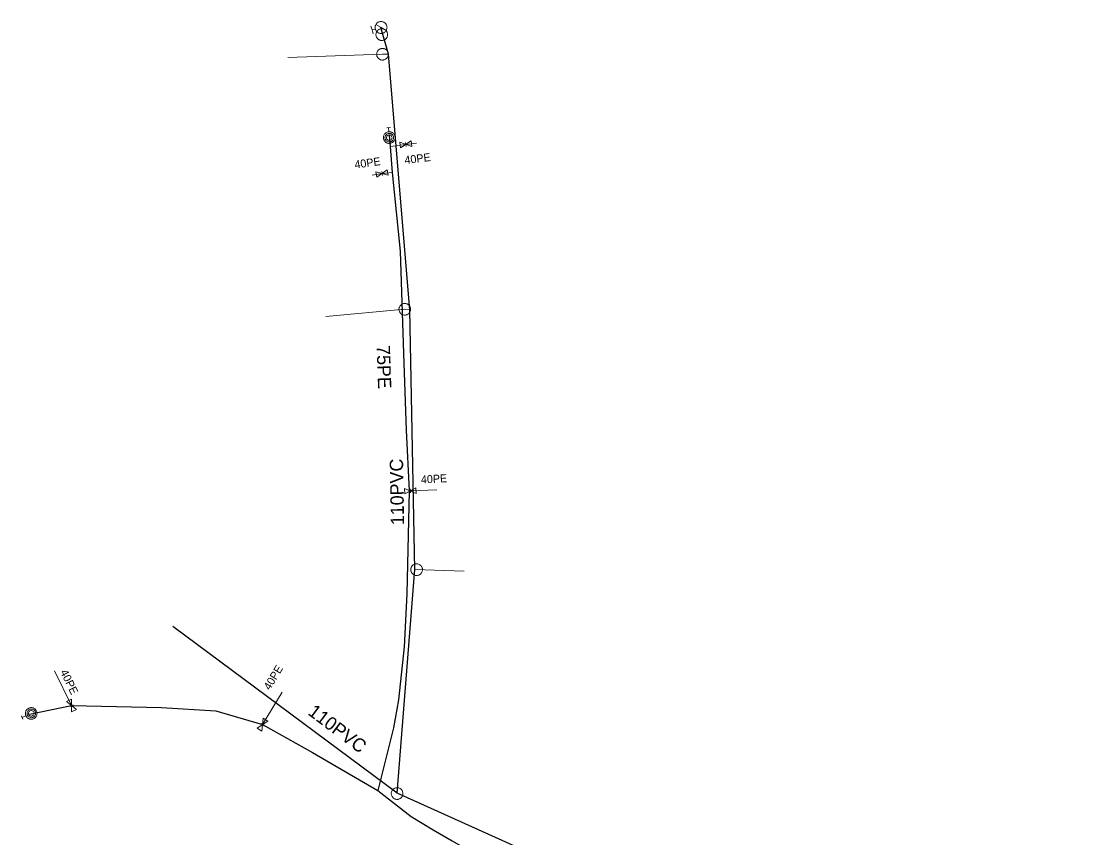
# Model space of a CAD drawing. Extents: x -741806 to -738704, y -1059275 to -1055387.
# Drawn here: x -740454.2 to -740373.8, y -1056915.4 to -1056854.3 of the extents above; entities that cross this region are included whole.
import ezdxf

# ---------------------------------------------------------------- set-up
doc = ezdxf.new("R2010")
doc.units = 0
doc.header["$LTSCALE"] = 0.4
for name, color, linetype, lineweight in [('2', 7, 'Continuous', 25), ('21', 7, 'Continuous', 13), ('37', 7, 'Continuous', 13), ('50', 7, 'Continuous', 13), ('51', 7, 'Continuous', 13), ('52', 7, 'Continuous', 25), ('56', 7, 'Continuous', 13)]:
    doc.layers.add(name, color=color, linetype=linetype, lineweight=lineweight)
for name, color, linetype in [('5', 7, 'Continuous'), ('53', 7, 'Continuous'), ('55', 7, 'Continuous')]:
    doc.layers.add(name, color=color, linetype=linetype)

msp = doc.modelspace()

# ---------------------------------------------------------------- linework, layer by layer
at = {"layer": '2'}
for points in [[(-740426.68, -1056862.84), (-740426.59, -1056863.659), (-740426.449, -1056865.61), (-740425.859, -1056871.5), (-740425.6, -1056879.159), (-740425.39, -1056884.909), (-740425.17, -1056889.46), (-740425.359, -1056897.179), (-740425.55, -1056901.139), (-740425.969, -1056905.1), (-740426.35, -1056907.2), (-740427.53, -1056911.899)], [(-740453.64, -1056906.19), (-740450.48, -1056905.54), (-740443.73, -1056905.679), (-740439.66, -1056905.94), (-740436.17, -1056906.97), (-740432.41, -1056909.06), (-740427.53, -1056911.899), (-740425.02, -1056913.86), (-740423.37, -1056914.86), (-740421.949, -1056915.679), (-740419.82, -1056916.909), (-740414.8, -1056920.01), (-740409.68, -1056923.179), (-740404.68, -1056925.79), (-740403.129, -1056927.36)]]:
    msp.add_lwpolyline(points, dxfattribs=at)
at = {"layer": '21'}
msp.add_line((-740424.752, -1056895.348), (-740421.048, -1056895.46), dxfattribs=at)
for points in [[(-740426.723, -1056856.754), (-740427.177, -1056856.75), (-740434.278, -1056856.993)], [(-740425.138, -1056875.886), (-740425.504, -1056875.855), (-740431.427, -1056876.394)]]:
    msp.add_lwpolyline(points, dxfattribs=at)
at = {"layer": '37'}
for p, q in [((-740426.856, -1056862.262), (-740426.585, -1056862.245)), ((-740426.702, -1056862.554), (-740426.721, -1056862.256)), ((-740425.43, -1056863.499), (-740425.446, -1056863.35)), ((-740425.43, -1056863.499), (-740425.413, -1056863.648)), ((-740427.209, -1056865.679), (-740427.235, -1056865.531)), ((-740427.209, -1056865.679), (-740427.183, -1056865.827)), ((-740425.09, -1056889.459), (-740425.096, -1056889.309)), ((-740425.09, -1056889.459), (-740425.083, -1056889.609)), ((-740450.48, -1056905.54), (-740450.615, -1056905.605)), ((-740450.48, -1056905.54), (-740450.345, -1056905.474)), ((-740454.124, -1056906.549), (-740454.231, -1056906.3)), ((-740453.901, -1056906.306), (-740454.175, -1056906.424)), ((-740436.17, -1056906.969), (-740436.298, -1056906.892)), ((-740436.17, -1056906.969), (-740436.042, -1056907.047))]:
    msp.add_line(p, q, dxfattribs=at)
for points in [[(-740426.234, -1056862.962), (-740426.239, -1056862.917), (-740426.249, -1056862.873), (-740426.263, -1056862.829), (-740426.282, -1056862.788), (-740426.306, -1056862.748), (-740426.333, -1056862.711), (-740426.364, -1056862.678), (-740426.398, -1056862.647), (-740426.436, -1056862.621), (-740426.475, -1056862.599), (-740426.518, -1056862.58), (-740426.562, -1056862.566), (-740426.606, -1056862.557), (-740426.652, -1056862.553), (-740426.698, -1056862.554), (-740426.743, -1056862.558), (-740426.788, -1056862.568), (-740426.831, -1056862.583), (-740426.873, -1056862.603), (-740426.913, -1056862.626), (-740426.949, -1056862.654), (-740426.983, -1056862.684), (-740427.013, -1056862.719), (-740427.04, -1056862.756), (-740427.062, -1056862.796), (-740427.08, -1056862.838), (-740427.094, -1056862.881), (-740427.103, -1056862.927), (-740427.107, -1056862.972), (-740427.107, -1056863.019), (-740427.101, -1056863.063), (-740427.091, -1056863.108), (-740427.076, -1056863.152), (-740427.058, -1056863.193), (-740427.034, -1056863.232), (-740427.007, -1056863.27), (-740426.976, -1056863.303), (-740426.942, -1056863.334), (-740426.904, -1056863.359), (-740426.864, -1056863.382), (-740426.822, -1056863.4), (-740426.778, -1056863.414), (-740426.734, -1056863.423), (-740426.688, -1056863.428), (-740426.642, -1056863.427), (-740426.596, -1056863.422), (-740426.552, -1056863.411), (-740426.509, -1056863.397), (-740426.467, -1056863.378), (-740426.427, -1056863.354), (-740426.391, -1056863.327), (-740426.357, -1056863.296), (-740426.327, -1056863.261), (-740426.3, -1056863.225), (-740426.278, -1056863.184), (-740426.259, -1056863.142), (-740426.246, -1056863.099), (-740426.237, -1056863.053), (-740426.233, -1056863.008), (-740426.234, -1056862.963)], [(-740453.674, -1056905.729), (-740453.714, -1056905.748), (-740453.753, -1056905.772), (-740453.789, -1056905.801), (-740453.822, -1056905.832), (-740453.851, -1056905.868), (-740453.877, -1056905.906), (-740453.898, -1056905.947), (-740453.915, -1056905.989), (-740453.927, -1056906.033), (-740453.935, -1056906.078), (-740453.938, -1056906.124), (-740453.937, -1056906.17), (-740453.93, -1056906.215), (-740453.919, -1056906.26), (-740453.903, -1056906.303), (-740453.883, -1056906.344), (-740453.859, -1056906.383), (-740453.83, -1056906.418), (-740453.798, -1056906.451), (-740453.762, -1056906.481), (-740453.724, -1056906.506), (-740453.684, -1056906.528), (-740453.641, -1056906.544), (-740453.598, -1056906.557), (-740453.552, -1056906.564), (-740453.506, -1056906.567), (-740453.461, -1056906.566), (-740453.415, -1056906.559), (-740453.371, -1056906.548), (-740453.327, -1056906.532), (-740453.287, -1056906.512), (-740453.249, -1056906.487), (-740453.212, -1056906.459), (-740453.18, -1056906.427), (-740453.15, -1056906.392), (-740453.124, -1056906.354), (-740453.104, -1056906.313), (-740453.086, -1056906.271), (-740453.075, -1056906.227), (-740453.067, -1056906.182), (-740453.063, -1056906.136), (-740453.065, -1056906.09), (-740453.072, -1056906.045), (-740453.082, -1056906), (-740453.099, -1056905.957), (-740453.119, -1056905.916), (-740453.144, -1056905.878), (-740453.171, -1056905.841), (-740453.204, -1056905.809), (-740453.239, -1056905.779), (-740453.277, -1056905.754), (-740453.317, -1056905.732), (-740453.36, -1056905.716), (-740453.404, -1056905.703), (-740453.45, -1056905.695), (-740453.496, -1056905.692), (-740453.54, -1056905.694), (-740453.587, -1056905.701), (-740453.631, -1056905.712), (-740453.673, -1056905.728)]]:
    msp.add_lwpolyline(points, dxfattribs=at)
for points in [[(-740426.347, -1056862.978), (-740426.357, -1056862.917), (-740426.379, -1056862.859), (-740426.411, -1056862.806), (-740426.453, -1056862.76), (-740426.503, -1056862.723), (-740426.558, -1056862.696), (-740426.618, -1056862.681), (-740426.681, -1056862.677), (-740426.742, -1056862.686), (-740426.801, -1056862.705), (-740426.855, -1056862.736), (-740426.902, -1056862.777), (-740426.94, -1056862.826), (-740426.968, -1056862.881), (-740426.986, -1056862.941), (-740426.991, -1056863.003), (-740426.984, -1056863.065), (-740426.965, -1056863.124), (-740426.936, -1056863.178), (-740426.896, -1056863.227), (-740426.849, -1056863.266), (-740426.794, -1056863.295), (-740426.735, -1056863.313), (-740426.673, -1056863.321), (-740426.611, -1056863.316), (-740426.551, -1056863.299), (-740426.496, -1056863.27), (-740426.447, -1056863.232), (-740426.406, -1056863.185), (-740426.375, -1056863.131), (-740426.355, -1056863.073), (-740426.347, -1056863.011)], [(-740426.461, -1056862.985), (-740426.47, -1056862.937), (-740426.49, -1056862.891), (-740426.521, -1056862.852), (-740426.56, -1056862.82), (-740426.606, -1056862.8), (-740426.655, -1056862.79), (-740426.704, -1056862.793), (-740426.753, -1056862.808), (-740426.795, -1056862.833), (-740426.831, -1056862.868), (-740426.857, -1056862.91), (-740426.873, -1056862.958), (-740426.877, -1056863.008), (-740426.869, -1056863.056), (-740426.849, -1056863.103), (-740426.82, -1056863.143), (-740426.78, -1056863.174), (-740426.736, -1056863.196), (-740426.687, -1056863.206), (-740426.637, -1056863.205), (-740426.589, -1056863.192), (-740426.545, -1056863.167), (-740426.509, -1056863.133), (-740426.482, -1056863.091), (-740426.465, -1056863.044), (-740426.46, -1056862.994)], [(-740425.021, -1056863.245), (-740425.838, -1056863.753), (-740425.884, -1056863.341), (-740424.975, -1056863.657)], [(-740427.601, -1056865.958), (-740426.818, -1056865.4), (-740426.746, -1056865.808), (-740427.673, -1056865.55)], [(-740424.665, -1056889.233), (-740425.514, -1056889.685), (-740425.532, -1056889.272), (-740424.647, -1056889.646)], [(-740450.856, -1056905.24), (-740450.104, -1056905.839), (-740450.476, -1056906.021), (-740450.484, -1056905.059)], [(-740453.62, -1056905.83), (-740453.675, -1056905.86), (-740453.722, -1056905.9), (-740453.761, -1056905.948), (-740453.79, -1056906.003), (-740453.809, -1056906.062), (-740453.815, -1056906.124), (-740453.809, -1056906.185), (-740453.792, -1056906.245), (-740453.763, -1056906.3), (-740453.725, -1056906.349), (-740453.678, -1056906.39), (-740453.624, -1056906.42), (-740453.565, -1056906.44), (-740453.503, -1056906.448), (-740453.441, -1056906.444), (-740453.381, -1056906.428), (-740453.325, -1056906.401), (-740453.276, -1056906.363), (-740453.235, -1056906.317), (-740453.202, -1056906.264), (-740453.181, -1056906.206), (-740453.172, -1056906.144), (-740453.175, -1056906.082), (-740453.189, -1056906.022), (-740453.214, -1056905.965), (-740453.25, -1056905.914), (-740453.295, -1056905.872), (-740453.348, -1056905.839), (-740453.405, -1056905.816), (-740453.467, -1056905.805), (-740453.529, -1056905.806), (-740453.589, -1056905.819)], [(-740453.575, -1056905.935), (-740453.618, -1056905.959), (-740453.655, -1056905.994), (-740453.681, -1056906.036), (-740453.697, -1056906.084), (-740453.701, -1056906.133), (-740453.694, -1056906.183), (-740453.674, -1056906.228), (-740453.645, -1056906.269), (-740453.607, -1056906.3), (-740453.562, -1056906.323), (-740453.513, -1056906.333), (-740453.463, -1056906.333), (-740453.415, -1056906.319), (-740453.371, -1056906.295), (-740453.334, -1056906.261), (-740453.307, -1056906.22), (-740453.29, -1056906.172), (-740453.284, -1056906.123), (-740453.291, -1056906.074), (-740453.309, -1056906.027), (-740453.338, -1056905.986), (-740453.376, -1056905.953), (-740453.421, -1056905.93), (-740453.469, -1056905.919), (-740453.519, -1056905.919), (-740453.567, -1056905.931)], [(-740436.122, -1056906.491), (-740436.217, -1056907.448), (-740436.572, -1056907.233), (-740435.768, -1056906.705)]]:
    msp.add_lwpolyline(points, close=True, dxfattribs=at)
at = {"layer": '50'}
for p, q in [((-740428.039, -1056854.633), (-740427.956, -1056854.928)), ((-740427.714, -1056854.86), (-740427.956, -1056854.928)), ((-740427.873, -1056855.225), (-740427.956, -1056854.928)), ((-740427.284, -1056854.738), (-740427.67, -1056854.519)), ((-740427.284, -1056854.738), (-740426.893, -1056854.958))]:
    msp.add_line(p, q, dxfattribs=at)
msp.add_lwpolyline([(-740427.4, -1056854.31), (-740427.447, -1056854.326), (-740427.49, -1056854.343), (-740427.531, -1056854.368), (-740427.567, -1056854.396), (-740427.601, -1056854.425), (-740427.633, -1056854.462), (-740427.659, -1056854.5), (-740427.683, -1056854.541), (-740427.703, -1056854.583), (-740427.715, -1056854.628), (-740427.725, -1056854.673), (-740427.732, -1056854.72), (-740427.729, -1056854.767), (-740427.724, -1056854.813), (-740427.715, -1056854.858), (-740427.699, -1056854.902), (-740427.682, -1056854.944), (-740427.657, -1056854.984), (-740427.629, -1056855.022), (-740427.597, -1056855.058), (-740427.563, -1056855.088), (-740427.525, -1056855.116), (-740427.484, -1056855.138), (-740427.443, -1056855.157), (-740427.397, -1056855.172), (-740427.352, -1056855.182), (-740427.306, -1056855.186), (-740427.258, -1056855.187), (-740427.212, -1056855.179), (-740427.166, -1056855.173), (-740427.121, -1056855.157), (-740427.079, -1056855.137), (-740427.04, -1056855.114), (-740427, -1056855.086), (-740426.967, -1056855.054), (-740426.935, -1056855.02), (-740426.909, -1056854.982), (-740426.884, -1056854.942), (-740426.866, -1056854.897), (-740426.853, -1056854.854), (-740426.843, -1056854.807), (-740426.839, -1056854.761), (-740426.838, -1056854.716), (-740426.843, -1056854.666), (-740426.853, -1056854.621), (-740426.868, -1056854.578), (-740426.888, -1056854.536), (-740426.911, -1056854.494), (-740426.938, -1056854.457), (-740426.971, -1056854.422), (-740427.005, -1056854.392), (-740427.044, -1056854.363), (-740427.083, -1056854.341), (-740427.125, -1056854.322), (-740427.171, -1056854.31), (-740427.216, -1056854.297), (-740427.263, -1056854.293), (-740427.309, -1056854.295), (-740427.355, -1056854.3)], close=True, dxfattribs=at)
at = {"layer": '51'}
for points in [[(-740426.793, -1056855.28), (-740426.794, -1056855.235), (-740426.802, -1056855.19), (-740426.814, -1056855.145), (-740426.83, -1056855.103), (-740426.851, -1056855.062), (-740426.875, -1056855.023), (-740426.905, -1056854.988), (-740426.937, -1056854.955), (-740426.973, -1056854.927), (-740427.011, -1056854.902), (-740427.052, -1056854.881), (-740427.095, -1056854.864), (-740427.139, -1056854.852), (-740427.184, -1056854.845), (-740427.23, -1056854.843), (-740427.276, -1056854.845), (-740427.321, -1056854.852), (-740427.365, -1056854.864), (-740427.407, -1056854.881), (-740427.449, -1056854.902), (-740427.487, -1056854.927), (-740427.522, -1056854.955), (-740427.554, -1056854.988), (-740427.584, -1056855.023), (-740427.608, -1056855.062), (-740427.63, -1056855.103), (-740427.646, -1056855.145), (-740427.657, -1056855.19), (-740427.665, -1056855.235), (-740427.668, -1056855.281), (-740427.665, -1056855.326), (-740427.657, -1056855.371), (-740427.646, -1056855.416), (-740427.63, -1056855.458), (-740427.608, -1056855.499), (-740427.584, -1056855.538), (-740427.554, -1056855.573), (-740427.522, -1056855.606), (-740427.487, -1056855.634), (-740427.449, -1056855.659), (-740427.407, -1056855.68), (-740427.365, -1056855.697), (-740427.321, -1056855.708), (-740427.276, -1056855.716), (-740427.23, -1056855.718), (-740427.184, -1056855.716), (-740427.139, -1056855.708), (-740427.095, -1056855.697), (-740427.052, -1056855.68), (-740427.011, -1056855.659), (-740426.973, -1056855.634), (-740426.937, -1056855.606), (-740426.905, -1056855.573), (-740426.875, -1056855.538), (-740426.851, -1056855.499), (-740426.83, -1056855.458), (-740426.814, -1056855.416), (-740426.802, -1056855.371), (-740426.794, -1056855.326), (-740426.793, -1056855.281)], [(-740427.613, -1056856.745), (-740427.612, -1056856.79), (-740427.605, -1056856.835), (-740427.594, -1056856.88), (-740427.578, -1056856.922), (-740427.557, -1056856.964), (-740427.533, -1056857.003), (-740427.504, -1056857.038), (-740427.472, -1056857.071), (-740427.437, -1056857.1), (-740427.399, -1056857.125), (-740427.358, -1056857.146), (-740427.315, -1056857.164), (-740427.271, -1056857.176), (-740427.226, -1056857.184), (-740427.18, -1056857.186), (-740427.134, -1056857.184), (-740427.089, -1056857.178), (-740427.045, -1056857.166), (-740427.002, -1056857.15), (-740426.961, -1056857.129), (-740426.923, -1056857.104), (-740426.886, -1056857.077), (-740426.854, -1056857.044), (-740426.825, -1056857.009), (-740426.799, -1056856.97), (-740426.778, -1056856.93), (-740426.762, -1056856.888), (-740426.749, -1056856.843), (-740426.742, -1056856.798), (-740426.739, -1056856.752), (-740426.741, -1056856.707), (-740426.748, -1056856.662), (-740426.759, -1056856.617), (-740426.775, -1056856.575), (-740426.796, -1056856.533), (-740426.82, -1056856.494), (-740426.849, -1056856.459), (-740426.881, -1056856.426), (-740426.916, -1056856.397), (-740426.954, -1056856.372), (-740426.995, -1056856.351), (-740427.038, -1056856.333), (-740427.082, -1056856.322), (-740427.127, -1056856.313), (-740427.173, -1056856.311), (-740427.219, -1056856.313), (-740427.264, -1056856.32), (-740427.308, -1056856.331), (-740427.351, -1056856.347), (-740427.392, -1056856.368), (-740427.43, -1056856.393), (-740427.467, -1056856.42), (-740427.499, -1056856.453), (-740427.528, -1056856.488), (-740427.554, -1056856.527), (-740427.575, -1056856.567), (-740427.591, -1056856.609), (-740427.604, -1056856.654), (-740427.611, -1056856.699), (-740427.613, -1056856.744)], [(-740425.939, -1056875.817), (-740425.941, -1056875.862), (-740425.938, -1056875.908), (-740425.929, -1056875.953), (-740425.917, -1056875.997), (-740425.9, -1056876.039), (-740425.878, -1056876.08), (-740425.852, -1056876.118), (-740425.823, -1056876.153), (-740425.789, -1056876.184), (-740425.754, -1056876.212), (-740425.714, -1056876.237), (-740425.673, -1056876.257), (-740425.63, -1056876.273), (-740425.586, -1056876.284), (-740425.54, -1056876.289), (-740425.494, -1056876.291), (-740425.449, -1056876.288), (-740425.404, -1056876.28), (-740425.36, -1056876.267), (-740425.317, -1056876.249), (-740425.277, -1056876.227), (-740425.239, -1056876.203), (-740425.204, -1056876.172), (-740425.172, -1056876.14), (-740425.144, -1056876.103), (-740425.12, -1056876.064), (-740425.1, -1056876.024), (-740425.085, -1056875.98), (-740425.074, -1056875.936), (-740425.067, -1056875.89), (-740425.066, -1056875.845), (-740425.069, -1056875.799), (-740425.077, -1056875.754), (-740425.09, -1056875.71), (-740425.107, -1056875.668), (-740425.129, -1056875.627), (-740425.155, -1056875.589), (-740425.184, -1056875.554), (-740425.217, -1056875.523), (-740425.253, -1056875.495), (-740425.292, -1056875.47), (-740425.334, -1056875.45), (-740425.377, -1056875.435), (-740425.421, -1056875.423), (-740425.466, -1056875.418), (-740425.512, -1056875.416), (-740425.558, -1056875.42), (-740425.603, -1056875.427), (-740425.647, -1056875.44), (-740425.69, -1056875.458), (-740425.73, -1056875.48), (-740425.768, -1056875.504), (-740425.803, -1056875.535), (-740425.834, -1056875.567), (-740425.863, -1056875.604), (-740425.887, -1056875.643), (-740425.906, -1056875.683), (-740425.922, -1056875.727), (-740425.933, -1056875.771), (-740425.939, -1056875.816)], [(-740424.183, -1056895.373), (-740424.183, -1056895.328), (-740424.189, -1056895.283), (-740424.2, -1056895.238), (-740424.214, -1056895.195), (-740424.234, -1056895.154), (-740424.258, -1056895.114), (-740424.286, -1056895.078), (-740424.317, -1056895.044), (-740424.352, -1056895.015), (-740424.389, -1056894.989), (-740424.429, -1056894.967), (-740424.472, -1056894.948), (-740424.516, -1056894.935), (-740424.56, -1056894.927), (-740424.606, -1056894.923), (-740424.652, -1056894.924), (-740424.697, -1056894.929), (-740424.742, -1056894.94), (-740424.785, -1056894.956), (-740424.827, -1056894.975), (-740424.866, -1056894.999), (-740424.902, -1056895.026), (-740424.935, -1056895.058), (-740424.966, -1056895.092), (-740424.992, -1056895.131), (-740425.014, -1056895.171), (-740425.031, -1056895.212), (-740425.045, -1056895.257), (-740425.053, -1056895.302), (-740425.057, -1056895.348), (-740425.056, -1056895.393), (-740425.05, -1056895.438), (-740425.039, -1056895.483), (-740425.025, -1056895.526), (-740425.005, -1056895.567), (-740424.981, -1056895.607), (-740424.953, -1056895.643), (-740424.922, -1056895.677), (-740424.887, -1056895.706), (-740424.85, -1056895.732), (-740424.81, -1056895.754), (-740424.767, -1056895.773), (-740424.724, -1056895.785), (-740424.679, -1056895.794), (-740424.633, -1056895.798), (-740424.587, -1056895.797), (-740424.542, -1056895.791), (-740424.497, -1056895.781), (-740424.454, -1056895.765), (-740424.412, -1056895.745), (-740424.373, -1056895.722), (-740424.337, -1056895.695), (-740424.304, -1056895.663), (-740424.274, -1056895.629), (-740424.247, -1056895.59), (-740424.225, -1056895.55), (-740424.208, -1056895.509), (-740424.194, -1056895.464), (-740424.186, -1056895.419), (-740424.183, -1056895.374)], [(-740426.479, -1056911.951), (-740426.495, -1056911.993), (-740426.507, -1056912.037), (-740426.515, -1056912.083), (-740426.518, -1056912.128), (-740426.515, -1056912.174), (-740426.509, -1056912.22), (-740426.497, -1056912.264), (-740426.481, -1056912.307), (-740426.46, -1056912.347), (-740426.435, -1056912.386), (-740426.407, -1056912.422), (-740426.374, -1056912.455), (-740426.339, -1056912.484), (-740426.301, -1056912.509), (-740426.26, -1056912.529), (-740426.217, -1056912.547), (-740426.173, -1056912.559), (-740426.128, -1056912.566), (-740426.082, -1056912.568), (-740426.036, -1056912.566), (-740425.991, -1056912.558), (-740425.947, -1056912.548), (-740425.904, -1056912.531), (-740425.863, -1056912.511), (-740425.824, -1056912.486), (-740425.788, -1056912.457), (-740425.757, -1056912.425), (-740425.727, -1056912.389), (-740425.702, -1056912.351), (-740425.681, -1056912.31), (-740425.665, -1056912.268), (-740425.653, -1056912.224), (-740425.645, -1056912.178), (-740425.642, -1056912.133), (-740425.645, -1056912.087), (-740425.652, -1056912.041), (-740425.664, -1056911.997), (-740425.679, -1056911.954), (-740425.701, -1056911.914), (-740425.725, -1056911.876), (-740425.754, -1056911.84), (-740425.786, -1056911.806), (-740425.821, -1056911.778), (-740425.859, -1056911.752), (-740425.9, -1056911.732), (-740425.943, -1056911.715), (-740425.987, -1056911.703), (-740426.032, -1056911.695), (-740426.078, -1056911.693), (-740426.124, -1056911.696), (-740426.169, -1056911.703), (-740426.213, -1056911.713), (-740426.256, -1056911.73), (-740426.297, -1056911.75), (-740426.336, -1056911.776), (-740426.372, -1056911.804), (-740426.404, -1056911.836), (-740426.433, -1056911.872), (-740426.458, -1056911.91), (-740426.478, -1056911.951)]]:
    msp.add_lwpolyline(points, dxfattribs=at)
at = {"layer": '52'}
msp.add_line((-740426.078, -1056912.101), (-740442.883, -1056899.612), dxfattribs=at)
for points in [[(-740426.078, -1056912.101), (-740424.752, -1056895.348), (-740425.138, -1056875.886), (-740426.723, -1056856.754), (-740427.289, -1056854.74)], [(-740316.568, -1056963.017), (-740375.68, -1056934.58), (-740380.818, -1056932.503), (-740426.078, -1056912.101)]]:
    msp.add_lwpolyline(points, dxfattribs=at)
at = {"layer": '56'}
for p, q in [((-740451.75, -1056902.929), (-740450.48, -1056905.54)), ((-740434.699, -1056904.54), (-740436.17, -1056906.97))]:
    msp.add_line(p, q, dxfattribs=at)
for points in [[(-740424.62, -1056863.409), (-740425.43, -1056863.5), (-740426.59, -1056863.659)], [(-740427.949, -1056865.81), (-740427.21, -1056865.679), (-740426.449, -1056865.61)], [(-740423.109, -1056889.37), (-740425.09, -1056889.46), (-740425.17, -1056889.46)]]:
    msp.add_lwpolyline(points, dxfattribs=at)

# ---------------------------------------------------------------- texts
at = {"layer": '5'}
msp.add_text('75PE', height=1, rotation=272, dxfattribs=at).set_placement((-740427.62, -1056878.558))
at = {"layer": '53'}
for rotation, p in [(91, (-740425.553, -1056892.017)), (323, (-740432.835, -1056906.162))]:
    msp.add_text('110PVC', height=1, rotation=rotation, dxfattribs=at).set_placement(p)
at = {"layer": '55'}
for rotation, p in [(8, (-740429.229, -1056865.32)), (7, (-740425.487, -1056864.981)), (3, (-740424.28, -1056888.908)), (296, (-740451.35, -1056903.015)), (59, (-740435.615, -1056904.432))]:
    msp.add_text('40PE', height=0.6, rotation=rotation, dxfattribs=at).set_placement(p)

doc.saveas('drawing.dxf')
